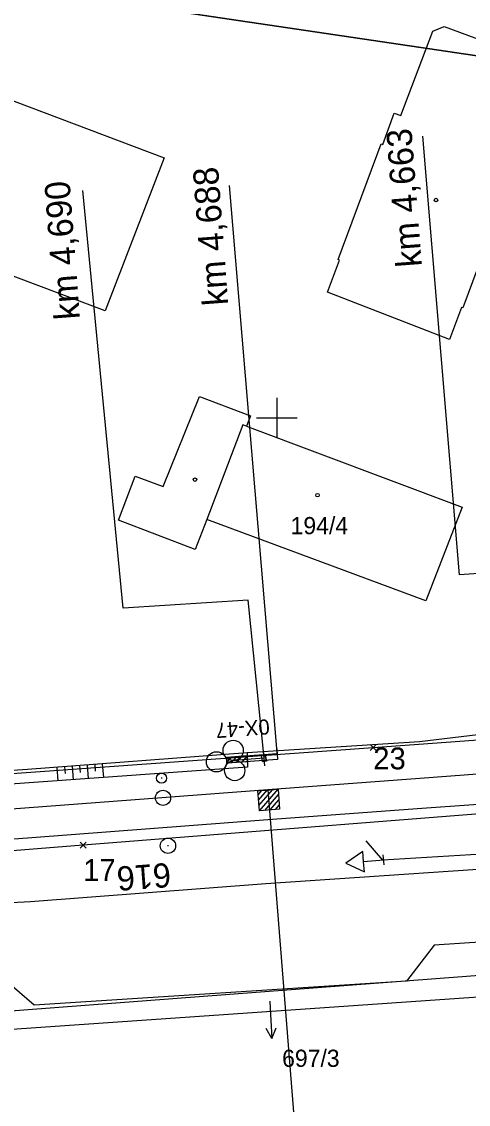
# Model space of a CAD drawing. Extents: x -779302 to -774398, y -1144902 to -1142831.
# Drawn here: x -774925.2 to -774881.1, y -1144467.9 to -1144360.8 of the extents above; entities that cross this region are included whole.
import ezdxf

# ---------------------------------------------------------------- set-up
doc = ezdxf.new("R2010")
doc.units = 0
for name, color, linetype in [('hektosit - Vrstva 5', 7, 'Continuous'), ('Hranice parcel', 7, 'Continuous'), ('legenda I_5_2 - Vrstva 53', 7, 'Continuous'), ('Parcelní čísla', 7, 'Continuous'), ('Pop  PČ popisy', 7, 'Continuous'), ('SŽDC', 7, 'Continuous'), ('Vnitřní kresba', 7, 'Continuous'), ('Vrstva 1', 7, 'Continuous'), ('zjednodus_g_situ-seda - Vrstva 1', 7, 'Continuous'), ('zjednodus_g_situ-seda - Vrstva 12', 7, 'Continuous'), ('zjednodus_g_situ-seda - Vrstva 13', 7, 'Continuous'), ('zjednodus_g_situ-seda - Vrstva 17', 7, 'Continuous'), ('zjednodus_g_situ-seda - Vrstva 3', 7, 'Continuous'), ('zjednodus_g_situ-seda - Vrstva 48', 7, 'Continuous'), ('zjednodus_g_situ-seda - Vrstva 49', 7, 'Continuous'), ('zjednodus_g_situ-seda - Vrstva 5', 7, 'Continuous'), ('zjednodus_g_situ-seda - Vrstva 51', 7, 'Continuous'), ('zjednodus_g_situ-seda - Vrstva 6', 7, 'Continuous'), ('zjednodus_g_situ-seda - Vrstva 63', 7, 'Continuous'), ('zjednodus_g_situ-seda - Vrstva 7', 7, 'Continuous'), ('zjednodus_g_situ-seda - Vrstva 8', 7, 'Continuous'), ('Značky budov', 7, 'Continuous')]:
    doc.layers.add(name, color=color, linetype=linetype)

msp = doc.modelspace()

# ---------------------------------------------------------------- linework, layer by layer
at = {"layer": 'hektosit - Vrstva 5'}
for p, q in [((-774900, -1144398), (-774900, -1144402)), ((-774902, -1144400), (-774898, -1144400))]:
    msp.add_line(p, q, dxfattribs=at)
at = {"layer": 'Hranice parcel'}
for p, q in [((-774934.19, -1144459.28), (-774865.74, -1144454.05)), ((-774934.36, -1144461.03), (-774875.06, -1144456.94))]:
    msp.add_line(p, q, dxfattribs=at)
for points in [[(-774952.35, -1144376.06), (-774948.54, -1144366.12), (-774946.53, -1144360.9), (-774911.14, -1144374.27), (-774916.98, -1144389.4), (-774952.35, -1144376.06)], [(-774885.25, -1144418.1), (-774906.94, -1144410.06), (-774908.07, -1144413.02), (-774915.67, -1144410.12), (-774914.01, -1144405.75), (-774911.26, -1144406.79), (-774907.66, -1144397.86), (-774902.6, -1144399.78), (-774903, -1144400.82), (-774881.66, -1144408.82), (-774885.25, -1144418.1)], [(-775003.31, -1144440.57), (-774957.77, -1144437.47), (-774890.46, -1144432.61), (-774871.96, -1144431.24)], [(-774832.04, -1144435.58), (-774869.06, -1144438.3), (-774919.16, -1144442.27), (-774942.23, -1144444.12), (-775006.07, -1144448.84), (-775047.73, -1144454.47), (-775049.08, -1144458.29), (-775076.86, -1144459.23)]]:
    msp.add_lwpolyline(points, dxfattribs=at)
at = {"layer": 'legenda I_5_2 - Vrstva 53'}
msp.add_lwpolyline([(-774957.77, -1144437.47), (-774890.46, -1144432.61), (-774871.96, -1144431.24), (-774870.21, -1144431.11), (-774832.66, -1144428.33), (-774832.04, -1144435.58), (-774869.06, -1144438.3), (-774919.16, -1144442.27), (-774942.23, -1144444.12)], dxfattribs=at)
at = {"layer": 'Pop  PČ popisy'}
for p, q in [((-774900.7, -1144457.7), (-774900.66, -1144458.39)), ((-774900.66, -1144458.39), (-774900.5, -1144461.39)), ((-774900.5, -1144461.39), (-774901.06, -1144460.41)), ((-774900.5, -1144461.39), (-774900.06, -1144460.36))]:
    msp.add_line(p, q, dxfattribs=at)
at = {"layer": 'SŽDC'}
for p, q in [((-774890.26, -1144432.81), (-774890.76, -1144432.31)), ((-774890.66, -1144432.81), (-774890.16, -1144432.31)), ((-774890.26, -1144432.41), (-774890.76, -1144432.91)), ((-774890.66, -1144432.41), (-774890.16, -1144432.91)), ((-774890.46, -1144432.61), (-774890.46, -1144432.61)), ((-774918.96, -1144442.47), (-774919.46, -1144441.97)), ((-774919.36, -1144442.47), (-774918.86, -1144441.97)), ((-774918.96, -1144442.07), (-774919.46, -1144442.57)), ((-774919.36, -1144442.07), (-774918.86, -1144442.57)), ((-774919.16, -1144442.27), (-774919.16, -1144442.27))]:
    msp.add_line(p, q, dxfattribs=at)
msp.add_lwpolyline([(-774957.77, -1144437.47), (-774890.46, -1144432.61), (-774871.96, -1144431.24), (-774870.21, -1144431.11), (-774832.66, -1144428.33), (-774832.04, -1144435.58), (-774869.06, -1144438.3), (-774919.16, -1144442.27), (-774942.23, -1144444.12)], dxfattribs=at)
at = {"layer": 'Vnitřní kresba'}
for p, q in [((-774884.58, -1144361.71), (-774883.44, -1144361.25)), ((-774883.44, -1144361.25), (-774874.4, -1144364.63)), ((-774887.73, -1144370.07), (-774884.58, -1144361.71)), ((-774889.53, -1144372.93), (-774888.38, -1144369.85)), ((-774888.38, -1144369.85), (-774887.73, -1144370.07)), ((-774893.94, -1144384.31), (-774889.67, -1144372.88)), ((-774889.67, -1144372.88), (-774889.53, -1144372.93)), ((-774877.41, -1144377.78), (-774881.61, -1144389.11)), ((-774894.99, -1144387.55), (-774893.8, -1144384.37)), ((-774893.8, -1144384.37), (-774893.94, -1144384.31)), ((-774882.93, -1144392.23), (-774894.99, -1144387.55)), ((-774881.75, -1144389.05), (-774882.93, -1144392.23)), ((-774881.61, -1144389.11), (-774881.75, -1144389.05)), ((-774903.37, -1144400.67), (-774906.94, -1144410.06)), ((-774903, -1144400.82), (-774903.37, -1144400.67))]:
    msp.add_line(p, q, dxfattribs=at)
at = {"layer": 'Vrstva 1'}
for points in [[(-774810.64, -1144374.46), (-775834.48, -1144222.92), (-775875.04, -1144496.94), (-774851.19, -1144648.48)], [(-774851.19, -1144648.48), (-775875.04, -1144496.94), (-775834.48, -1144222.92), (-774810.64, -1144374.46)]]:
    msp.add_lwpolyline(points, close=True, dxfattribs=at)
at = {"layer": 'zjednodus_g_situ-seda - Vrstva 1'}
msp.add_lwpolyline([(-774830.16, -1144431.48), (-774850.56, -1144433.02), (-774864.47, -1144434.06), (-774869.91, -1144434.47), (-774871.83, -1144434.62), (-774885.85, -1144435.68), (-774900.88, -1144436.8), (-774924.49, -1144438.59), (-774948.04, -1144440.36), (-774972.39, -1144442.2), (-774996.53, -1144444.02), (-775020.06, -1144445.79), (-775040.38, -1144447.31), (-775053.94, -1144448.33), (-775072.56, -1144449.73), (-775089.15, -1144450.96), (-775106.82, -1144452.3), (-775129.87, -1144454.04), (-775154.33, -1144455.87), (-775163.87, -1144456.59), (-775186.75, -1144458.31), (-775211.37, -1144460.17), (-775237.52, -1144462.13)], dxfattribs=at)
at = {"layer": 'zjednodus_g_situ-seda - Vrstva 12'}
msp.add_line((-774901.43, -1144433.98), (-774901.02, -1144433.94), dxfattribs=at)
for points in [[(-774901.02, -1144433.95), (-774901.42, -1144433.98), (-774901.51, -1144433.41), (-774901.14, -1144433.36), (-774901.02, -1144433.95)], [(-774901.42, -1144433.98), (-774901.43, -1144433.98), (-774901.51, -1144433.41)], [(-774901.02, -1144433.95), (-774901.02, -1144433.94), (-774901.14, -1144433.36)]]:
    msp.add_lwpolyline(points, dxfattribs=at)
at = {"layer": 'zjednodus_g_situ-seda - Vrstva 13'}
msp.add_lwpolyline([(-774871.7, -1144437.65), (-774885.67, -1144438.64), (-774900.9, -1144439.76), (-774924.23, -1144441.56), (-774947.71, -1144443.29), (-774972, -1144445.16), (-774996.17, -1144446.96), (-775023.26, -1144448.85)], dxfattribs=at)
at = {"layer": 'zjednodus_g_situ-seda - Vrstva 17'}
for points in [[(-774872.15, -1144430.41), (-774885.89, -1144432.05), (-774902.94, -1144433.13), (-774924.67, -1144434.79), (-774949.14, -1144436.4), (-774972.46, -1144437.97), (-774996.34, -1144439.6), (-775002.85, -1144440.11), (-775020.66, -1144440.35), (-775032.34, -1144440.73), (-775032.74, -1144440.94), (-775036.85, -1144438.2), (-775060.18, -1144440.14)], [(-774871.02, -1144442.65), (-774889.51, -1144443.75), (-774891.18, -1144441.84)]]:
    msp.add_lwpolyline(points, dxfattribs=at)
at = {"layer": 'zjednodus_g_situ-seda - Vrstva 3'}
for p, q in [((-774901.85, -1144437.29), (-774901.47, -1144436.85)), ((-774901.81, -1144437.82), (-774900.94, -1144436.81)), ((-774901.77, -1144438.35), (-774900.41, -1144436.77)), ((-774901.73, -1144438.87), (-774899.88, -1144436.73)), ((-774901.2, -1144438.83), (-774899.84, -1144437.26)), ((-774900.88, -1144436.8), (-774896.8, -1144488.33)), ((-774900.67, -1144438.79), (-774899.8, -1144437.79)), ((-774900.14, -1144438.75), (-774899.76, -1144438.32))]:
    msp.add_line(p, q, dxfattribs=at)
msp.add_lwpolyline([(-774901.88, -1144436.88), (-774899.88, -1144436.73), (-774899.73, -1144438.72), (-774901.73, -1144438.87)], close=True, dxfattribs=at)
at = {"layer": 'zjednodus_g_situ-seda - Vrstva 48'}
for p, q in [((-774920.26, -1144434.45), (-774920.15, -1144435.8)), ((-774919.51, -1144434.4), (-774919.46, -1144435.07)), ((-774918.76, -1144434.34), (-774918.66, -1144435.69)), ((-774918.01, -1144434.28), (-774917.96, -1144434.96)), ((-774917.27, -1144434.22), (-774917.16, -1144435.59)), ((-774921.75, -1144434.57), (-774921.65, -1144435.91)), ((-774921.01, -1144434.51), (-774920.95, -1144435.18))]:
    msp.add_line(p, q, dxfattribs=at)
at = {"layer": 'zjednodus_g_situ-seda - Vrstva 49'}
for points in [[(-774902.94, -1144433.13), (-774924.67, -1144434.79), (-774949.14, -1144436.4), (-774972.46, -1144437.97), (-774996.9, -1144440.49), (-775020.67, -1144441.55), (-775032.62, -1144441.6), (-775035.33, -1144441.27), (-775039.77, -1144441.73), (-775039.6, -1144444.15)], [(-774902.94, -1144433.13), (-774902.91, -1144434.56), (-774924.5, -1144436.11), (-774948.64, -1144437.83), (-774972.47, -1144439.52), (-774996.85, -1144441.35), (-775020.54, -1144443.02), (-775039, -1144443.02)]]:
    msp.add_lwpolyline(points, dxfattribs=at)
at = {"layer": 'zjednodus_g_situ-seda - Vrstva 5'}
msp.add_lwpolyline([(-774874.39, -1144431.65), (-774875.72, -1144415.08), (-774881.92, -1144415.53), (-774885.56, -1144372.1)], dxfattribs=at)
at = {"layer": 'zjednodus_g_situ-seda - Vrstva 51'}
for p, q in [((-774889.38, -1144444.23), (-774889.47, -1144443.24)), ((-774924.02, -1144458.11), (-774927.81, -1144454.84)), ((-774887.16, -1144455.73), (-774924.02, -1144458.11))]:
    msp.add_line(p, q, dxfattribs=at)
for points in [[(-775004.35, -1144452.66), (-774971.59, -1144450.6), (-774948.72, -1144449.09), (-774924.37, -1144447.83), (-774901.09, -1144446.06), (-774870.84, -1144444.01), (-774869.28, -1144443.86), (-774842.28, -1144442.2), (-774812.69, -1144440.35), (-774782.54, -1144438.6), (-774746.42, -1144436.35)], [(-774889.43, -1144443.74), (-774891.42, -1144443.91), (-774891.51, -1144442.91), (-774893.16, -1144444.06), (-774891.33, -1144444.91), (-774891.42, -1144443.91)], [(-774745.99, -1144443.71), (-774781.92, -1144445.7), (-774812.01, -1144447.53), (-774841.78, -1144449.45), (-774866.91, -1144451), (-774884.45, -1144452.18), (-774887.16, -1144455.73)]]:
    msp.add_lwpolyline(points, dxfattribs=at)
at = {"layer": 'zjednodus_g_situ-seda - Vrstva 6'}
for p, q in [((-774899.95, -1144433.49), (-774904.69, -1144376.98)), ((-774904.5, -1144433.53), (-774904.93, -1144434.02)), ((-774903.97, -1144433.49), (-774904.52, -1144434.13)), ((-774903.44, -1144433.45), (-774904, -1144434.09)), ((-774902.96, -1144433.46), (-774903.47, -1144434.05))]:
    msp.add_line(p, q, dxfattribs=at)
msp.add_lwpolyline([(-774900.02, -1144432.59), (-774899.97, -1144433.19), (-774899.93, -1144433.79), (-774904.91, -1144434.16), (-774904.96, -1144433.56), (-774899.97, -1144433.19)], dxfattribs=at)
msp.add_lwpolyline([(-774902.97, -1144433.41), (-774902.92, -1144434.01), (-774904.91, -1144434.16), (-774904.96, -1144433.56)], close=True, dxfattribs=at)
at = {"layer": 'zjednodus_g_situ-seda - Vrstva 63'}
msp.add_line((-774910.72, -1144442.33), (-774910.81, -1144442.34), dxfattribs=at)
msp.add_circle((-774910.77, -1144442.33), 0.756, dxfattribs=at)
at = {"layer": 'zjednodus_g_situ-seda - Vrstva 7'}
msp.add_line((-774911.35, -1144435.64), (-774911.45, -1144435.65), dxfattribs=at)
for centre, radius in [((-774911.4, -1144435.64), 0.5), ((-774911.26, -1144437.59), 0.75)]:
    msp.add_circle(centre, radius, dxfattribs=at)
at = {"layer": 'zjednodus_g_situ-seda - Vrstva 8'}
for p, q in [((-774901.2, -1144434.41), (-774901.31, -1144432.92)), ((-774901.25, -1144433.67), (-774904.25, -1144433.89))]:
    msp.add_line(p, q, dxfattribs=at)
msp.add_lwpolyline([(-774901.25, -1144433.67), (-774902.83, -1144418.04), (-774915.19, -1144418.83), (-774919.2, -1144377.48)], dxfattribs=at)
for centre in [(-774904.32, -1144432.89), (-774905.97, -1144434.02), (-774904.17, -1144434.89)]:
    msp.add_circle(centre, 1, dxfattribs=at)
at = {"layer": 'Značky budov'}
for centre in [(-774884.25, -1144378.43), (-774908.09, -1144406.1), (-774895.98, -1144407.64)]:
    msp.add_circle(centre, 0.175, dxfattribs=at)

# ---------------------------------------------------------------- texts
at = {"layer": 'Parcelní čísla'}
for s, p in [('194/4', (-774898.64, -1144411.5)), ('697/3', (-774899.48, -1144464.21))]:
    msp.add_text(s, height=1.7, dxfattribs=at).set_placement(p)
at = {"layer": 'SŽDC'}
for s, p in [('23', (-774890.46, -1144434.77)), ('17', (-774919.16, -1144445.81))]:
    msp.add_text(s, height=2.16, dxfattribs=at).set_placement(p)
at = {"layer": 'zjednodus_g_situ-seda - Vrstva 5'}
msp.add_text('km 4,663', height=2.5, rotation=94.3422, dxfattribs=at).set_placement((-774885.65, -1144384.98))
at = {"layer": 'zjednodus_g_situ-seda - Vrstva 6'}
msp.add_text('km 4,688', height=2.5, rotation=94.2701, dxfattribs=at).set_placement((-774904.8, -1144388.79))
at = {"layer": 'zjednodus_g_situ-seda - Vrstva 63'}
msp.add_text('616', height=2.4, rotation=184.3187, dxfattribs=at).set_placement((-774910.57, -1144444.01))
at = {"layer": 'zjednodus_g_situ-seda - Vrstva 8'}
for s, height, rotation, p in [('km 4,690', 2.5, 94.3187, (-774919.47, -1144390.18)), ('0X-47', 1.5, 184.3187, (-774900.77, -1144429.79))]:
    msp.add_text(s, height=height, rotation=rotation, dxfattribs=at).set_placement(p)

doc.saveas('drawing.dxf')
